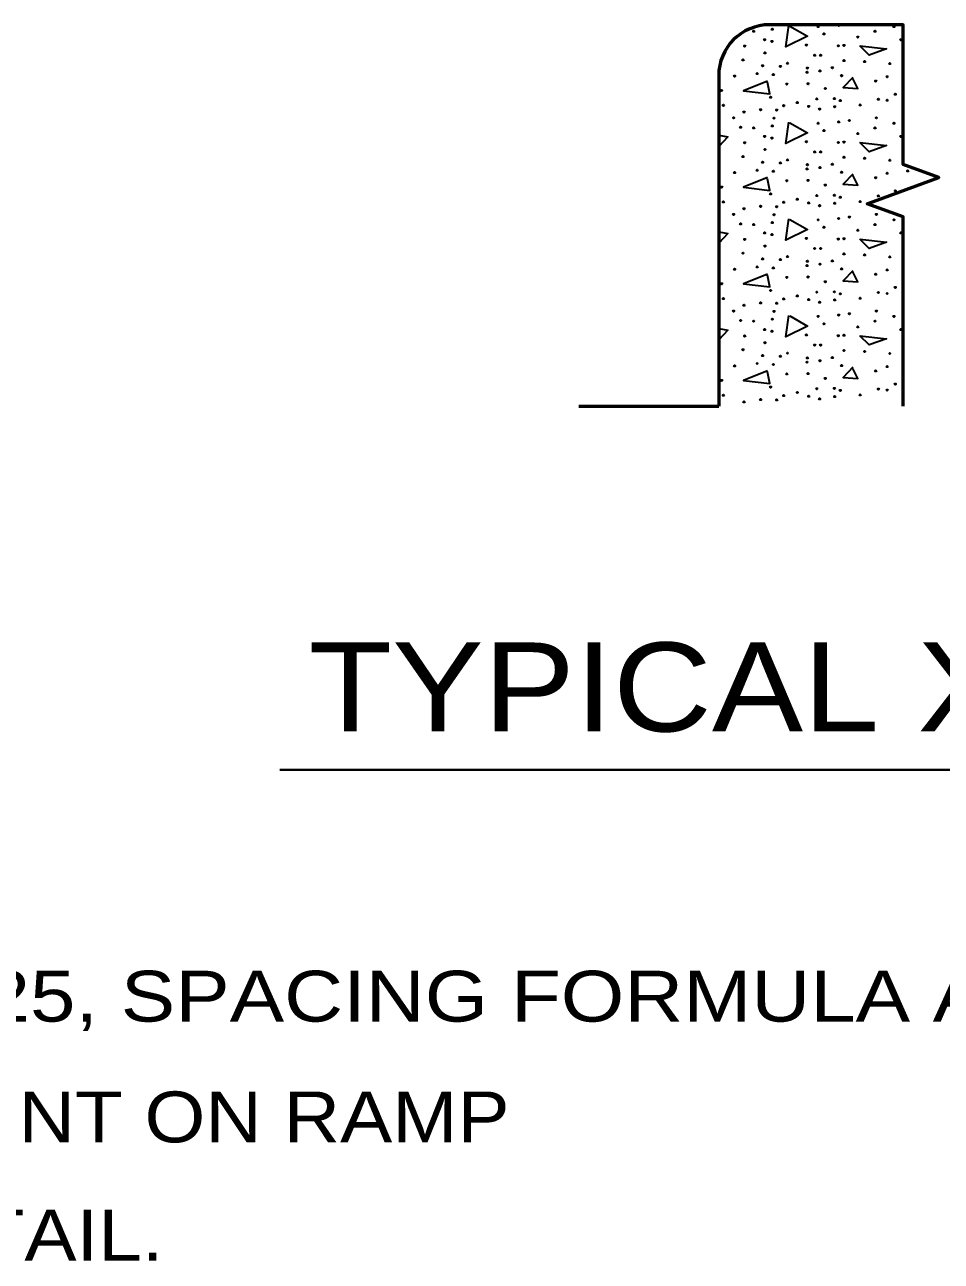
# Model space of a CAD drawing. Extents: x -89 to 766, y -60 to 484.
# Drawn here: x 590.4 to 633.6, y 85.1 to 143.4 of the extents above; entities that cross this region are included whole.
import ezdxf

# ---------------------------------------------------------------- set-up
doc = ezdxf.new("R2010")
doc.units = 0
doc.header["$LTSCALE"] = 1.1
doc.layers.add('1', color=7, linetype='Continuous', lineweight=35)

msp = doc.modelspace()

# ---------------------------------------------------------------- linework, layer by layer
at = {"layer": '1', "lineweight": 53}
for p in [(623.112, 141.017), (616.512, 125.417)]:
    msp.add_line(p, (623.112, 125.417), dxfattribs=at)
at = {"layer": '1', "lineweight": 40}
msp.add_line((602.417, 108.258), (698.915, 108.258), dxfattribs=at)
at = {"layer": '1', "lineweight": 53}
msp.add_lwpolyline([(631.812, 125.417), (631.812, 134.355), (630.121, 134.97), (633.504, 136.201), (631.812, 136.817), (631.812, 143.417), (625.512, 143.417)], dxfattribs=at)
at = {"layer": '1'}
for points in [[(626.466, 143.352), (627.306, 142.872), (626.274, 142.368), (626.418, 143.376)], [(625.41, 140.76), (624.282, 140.304), (625.53, 140.16), (625.41, 140.712)], [(629.442, 140.928), (628.986, 140.448), (629.682, 140.4), (629.442, 140.88)], [(626.466, 138.792), (627.306, 138.312), (626.274, 137.808), (626.418, 138.816)], [(623.112, 138.208), (623.538, 138.12), (623.112, 137.664)], [(625.41, 136.2), (624.282, 135.744), (625.53, 135.6), (625.41, 136.152)], [(629.442, 136.368), (628.986, 135.888), (629.682, 135.84), (629.442, 136.32)], [(626.466, 134.232), (627.306, 133.752), (626.274, 133.248), (626.418, 134.256)], [(623.112, 133.648), (623.538, 133.56), (623.112, 133.104)], [(625.41, 131.64), (624.282, 131.184), (625.53, 131.04), (625.41, 131.592)], [(629.442, 131.808), (628.986, 131.328), (629.682, 131.28), (629.442, 131.76)], [(626.466, 129.672), (627.306, 129.192), (626.274, 128.688), (626.418, 129.696)], [(623.112, 129.088), (623.538, 129), (623.112, 128.544)], [(629.442, 127.248), (628.986, 126.768), (629.682, 126.72), (629.442, 127.2)], [(625.41, 127.08), (624.282, 126.624), (625.53, 126.48), (625.41, 127.032)]]:
    msp.add_lwpolyline(points, dxfattribs=at)
for points in [[(629.778, 142.416), (631.026, 142.272), (630.21, 141.984)], [(629.778, 137.856), (631.026, 137.712), (630.21, 137.424)], [(629.778, 133.296), (631.026, 133.152), (630.21, 132.864)], [(629.778, 128.736), (631.026, 128.592), (630.21, 128.304)]]:
    msp.add_lwpolyline(points, close=True, dxfattribs=at)
for centre in [(624.769, 143.107), (625.643, 143.202), (627.806, 143.33), (628.077, 142.98), (630.487, 143.107), (631.378, 143.33), (624.339, 142.407), (625.278, 142.709), (625.627, 142.63), (627.25, 142.455), (628.753, 142.42), (629.024, 142.439), (629.676, 142.837), (631.712, 142.709), (625.294, 142.089), (627.647, 141.977), (627.918, 141.977), (624.26, 141.755), (625.182, 141.484), (626.025, 141.452), (626.359, 141.596), (627.297, 141.373), (627.886, 141.236), (628.474, 141.389), (629.024, 141.723), (629.994, 141.675), (631.187, 141.58), (623.862, 140.997), (624.928, 141.108), (625.691, 141.061), (626.327, 140.615), (627.281, 141.172), (627.329, 140.631), (628.913, 141.013), (630.519, 140.758), (631.06, 140.965), (623.194, 140.313), (623.258, 140.313), (628.14, 140.408), (631.441, 140.138), (623.337, 139.613), (625.564, 139.995), (626.184, 139.597), (626.82, 139.74), (627.361, 139.565), (627.743, 139.915), (628.57, 139.931), (628.586, 139.549), (628.849, 139.836), (629.787, 139.629), (630.646, 139.899), (631.06, 139.852), (623.814, 139.024), (624.307, 139.295), (625.087, 139.406), (625.723, 139.008), (625.85, 139.39), (627.87, 139.438), (629.279, 138.897), (630.551, 139.024), (624.148, 138.579), (624.769, 138.547), (625.643, 138.642), (627.806, 138.77), (628.077, 138.42), (628.776, 138.833), (629.676, 138.277), (630.487, 138.547), (631.378, 138.77), (624.339, 137.847), (625.278, 138.149), (625.627, 138.07), (627.25, 137.895), (628.753, 137.86), (629.024, 137.879), (631.712, 138.149), (624.26, 137.195), (625.294, 137.529), (627.647, 137.417), (627.918, 137.417), (629.024, 137.163), (629.994, 137.115), (624.928, 136.548), (625.182, 136.924), (626.025, 136.892), (626.359, 137.036), (627.281, 136.612), (627.297, 136.813), (627.886, 136.676), (628.474, 136.829), (631.187, 137.02), (623.862, 136.437), (625.691, 136.501), (626.327, 136.055), (627.329, 136.071), (628.913, 136.453), (630.519, 136.198), (631.06, 136.405), (632.03, 136.516), (623.194, 135.753), (623.258, 135.753), (625.564, 135.435), (628.14, 135.848), (628.57, 135.371), (631.441, 135.578), (623.337, 135.053), (625.087, 134.846), (625.85, 134.83), (626.184, 135.037), (626.82, 135.18), (627.361, 135.005), (627.743, 135.355), (627.87, 134.878), (628.586, 134.989), (628.849, 135.276), (629.787, 135.069), (630.646, 135.339), (623.814, 134.464), (624.307, 134.735), (625.723, 134.448), (627.806, 134.21), (628.776, 134.273), (629.279, 134.337), (630.551, 134.464), (631.378, 134.21), (624.148, 134.019), (624.769, 133.987), (625.643, 134.082), (628.077, 133.86), (629.676, 133.717), (630.487, 133.987), (624.339, 133.287), (625.278, 133.589), (625.627, 133.51), (627.25, 133.335), (628.753, 133.3), (629.024, 133.319), (631.712, 133.589), (624.26, 132.635), (625.294, 132.969), (626.359, 132.476), (627.647, 132.857), (627.918, 132.857), (629.024, 132.603), (629.994, 132.555), (631.187, 132.46), (623.862, 131.877), (624.928, 131.988), (625.182, 132.364), (625.691, 131.941), (626.025, 132.332), (627.281, 132.052), (627.297, 132.253), (627.886, 132.116), (628.474, 132.269), (628.913, 131.893), (626.327, 131.495), (627.329, 131.511), (628.14, 131.288), (630.519, 131.638), (631.06, 131.845), (623.194, 131.193), (623.258, 131.193), (625.564, 130.875), (627.743, 130.795), (628.57, 130.811), (628.849, 130.716), (630.646, 130.779), (631.06, 130.732), (631.441, 131.018), (623.337, 130.493), (624.307, 130.175), (625.087, 130.286), (625.85, 130.27), (626.184, 130.477), (626.82, 130.62), (627.361, 130.445), (627.87, 130.318), (628.586, 130.429), (629.787, 130.509), (623.814, 129.904), (625.723, 129.888), (627.806, 129.65), (628.776, 129.713), (629.279, 129.777), (630.551, 129.904), (631.378, 129.65), (624.148, 129.459), (624.769, 129.427), (625.278, 129.029), (625.627, 128.95), (625.643, 129.522), (628.077, 129.3), (629.676, 129.157), (630.487, 129.427), (631.712, 129.029), (624.339, 128.727), (625.294, 128.409), (627.25, 128.775), (628.753, 128.74), (629.024, 128.759), (624.26, 128.075), (625.182, 127.804), (626.359, 127.916), (627.647, 128.297), (627.918, 128.297), (629.024, 128.043), (629.994, 127.995), (631.187, 127.9), (623.862, 127.317), (624.928, 127.428), (625.691, 127.381), (626.025, 127.772), (627.281, 127.492), (627.297, 127.693), (627.886, 127.556), (628.474, 127.709), (628.913, 127.333), (631.06, 127.285), (623.194, 126.633), (623.258, 126.633), (626.327, 126.935), (627.329, 126.951), (628.14, 126.728), (630.519, 127.078), (625.564, 126.315), (626.82, 126.06), (627.743, 126.235), (628.57, 126.251), (628.849, 126.156), (630.646, 126.219), (631.06, 126.172), (631.441, 126.458), (623.337, 125.933), (624.307, 125.615), (625.087, 125.726), (625.85, 125.71), (626.184, 125.917), (627.361, 125.885), (627.87, 125.758), (628.586, 125.869), (629.787, 125.949)]:
    msp.add_circle(centre, 0.0318, dxfattribs=at)
at = {"layer": '1', "lineweight": 53}
msp.add_arc((625.512, 141.017), 2.4, 90, 180, dxfattribs=at)
at = {"layer": '1'}
for centre, start, end in [((628.776, 143.393), 131.90562, 48.09438), ((631.06, 135.292), 57.03221, 162.96854)]:
    msp.add_arc(centre, 0.0318, start, end, dxfattribs=at)

# ---------------------------------------------------------------- texts
for s, height, width, p in [('TYPICAL XR-3 INSTALLATION', 4.2, 1.15, (603.769, 110.062)), ('XR-9 FROM .064 TO .125, SPACING FORMULA ADDED, MEDIAN DETAIL.', 2.4, 1.2, (548.036, 96.37)), ('DELINEATOR PLACEMENT ON RAMP', 2.4, 1.15, (547.831, 90.67)), ('XR-3 CONNECTION DETAIL.', 2.4, 1.15, (547.708, 85.093))]:
    msp.add_text(s, height=height, dxfattribs=dict(at, width=width)).set_placement(p)

doc.saveas('drawing.dxf')
